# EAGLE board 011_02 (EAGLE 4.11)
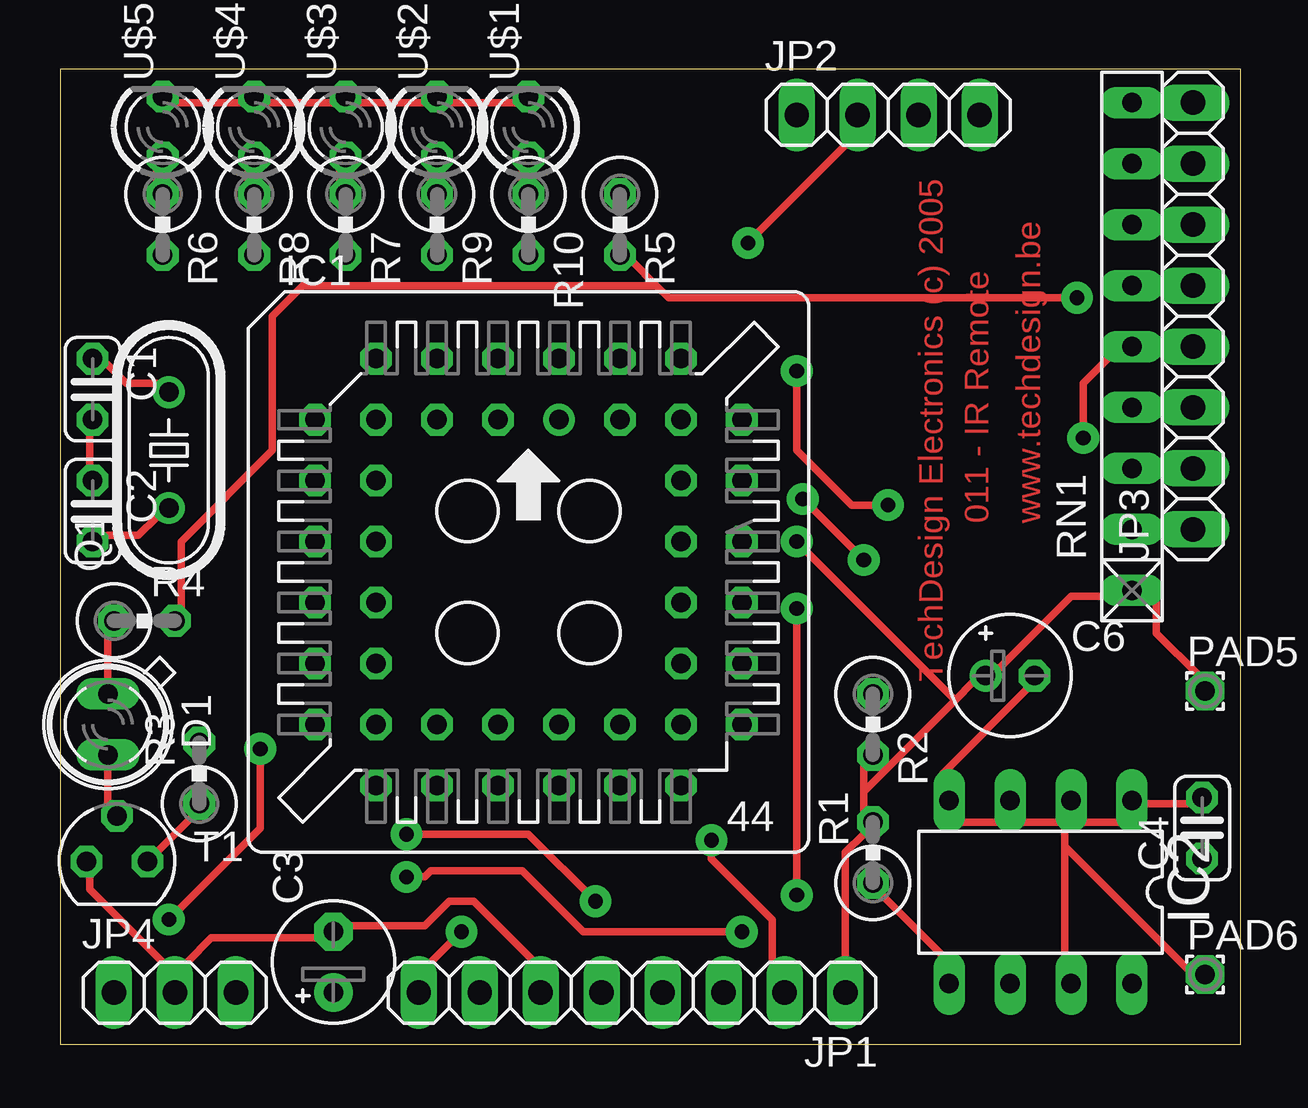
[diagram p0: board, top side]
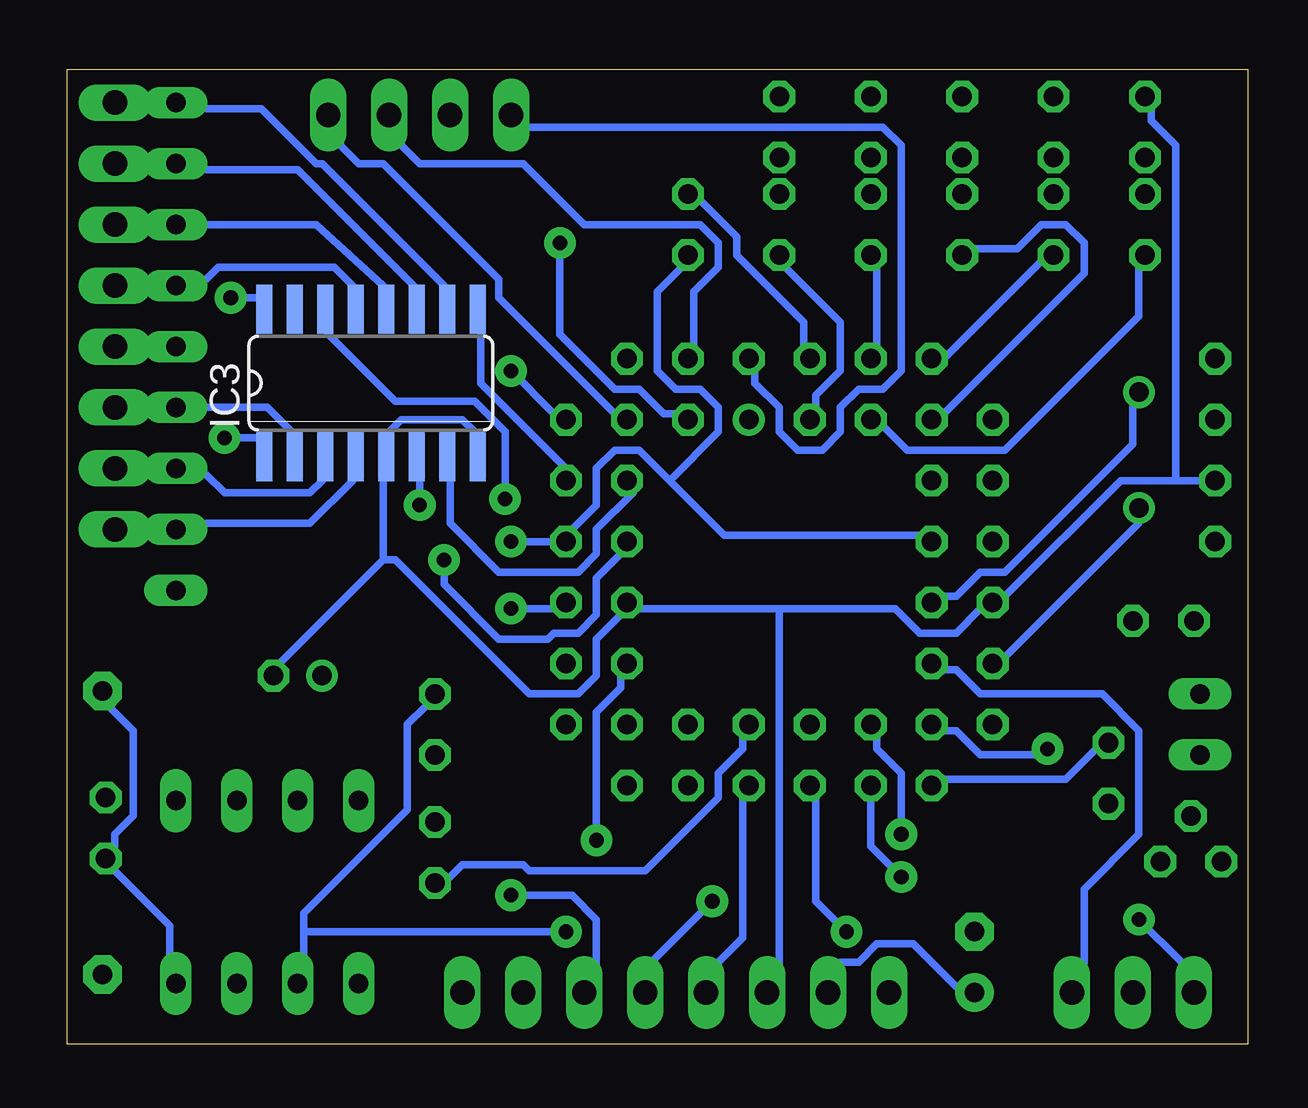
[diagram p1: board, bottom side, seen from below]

Size 49.2 x 40.63 mm. Coordinates in mm from the lower left corner, seen from the top.
Outline: 0,0 49.2,0 49.2,40.63 0,40.63 0,0
Copper layers (1*16): Top 0.035mm / dielectric 1.5mm / Bottom 0.035mm
Design rules "michel4": minimum track width 12mil, minimum drill 24mil, track to track 12mil, track to pad 12mil, pad to pad 12mil, via to via 12mil, smd to smd 10mil, copper to edge 40mil, drill to drill 8mil, minimum pad ring 10mil, minimum via ring 14mil, stop-mask expansion 4mil, vias tented up to drill 0mil, thermal gap 10mil
tRestrict: area 9.1,9.5 to 29.9,30.1; area 31.5,24.3 to 41.9,30.3

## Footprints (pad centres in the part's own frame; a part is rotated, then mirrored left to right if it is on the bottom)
C025-024X044 = drill 0.813 octagon: 1 -1.27,0; 2 1.27,0
E2,5-5 = drill 0.813 pad 1.6 round: + -1.27,0 | drill 0.813 pad 1.6 octagon: - 1.27,0
E2-5 = drill 0.813 pad 1.27 round: + -1.016,0 | drill 0.813 pad 1.27 octagon: - 1.016,0
SFH482 = drill 0.813 long: A -1.27,0; K 1.27,0
S44 = drill 0.813 round: 1 1.27,6.35 | drill 0.813 octagon: 2 -1.27,8.89; 3 -1.27,6.35; 4 -3.81,8.89; 5 -3.81,6.35; 6 -6.35,8.89; 7 -8.89,6.35; 8 -6.35,6.35; 9 -8.89,3.81; 10 -6.35,3.81; 11 -8.89,1.27; 12 -6.35,1.27; 13 -8.89,-1.27; 14 -6.35,-1.27; 15 -8.89,-3.81; 16 -6.35,-3.81; 17 -8.89,-6.35; 18 -6.35,-8.89; 19 -6.35,-6.35; 20 -3.81,-8.89; 21 -3.81,-6.35; 22 -1.27,-8.89; 23 -1.27,-6.35; 24 1.27,-8.89; 25 1.27,-6.35; 26 3.81,-8.89; 27 3.81,-6.35; 28 6.35,-8.89; 29 8.89,-6.35; 30 6.35,-6.35; 31 8.89,-3.81; 32 6.35,-3.81; 33 8.89,-1.27; 34 6.35,-1.27; 35 8.89,1.27; 36 6.35,1.27; 37 8.89,3.81; 38 6.35,3.81; 39 8.89,6.35; 40 6.35,8.89; 41 6.35,6.35; 42 3.81,8.89; 43 3.81,6.35; 44 1.27,8.89
DIL8 = drill 0.813 long: 1 -3.81,-3.81; 2 -1.27,-3.81; 3 1.27,-3.81; 4 3.81,-3.81; 5 3.81,3.81; 6 1.27,3.81; 7 -1.27,3.81; 8 -3.81,3.81
SO16 = smd 0.66 x 2.032: 1 -4.445,-3.073; 2 -3.175,-3.073; 3 -1.905,-3.073; 4 -0.635,-3.073; 5 0.635,-3.073; 6 1.905,-3.073; 7 3.175,-3.073; 8 4.445,-3.073; 9 4.445,3.073; 10 3.175,3.073; 11 1.905,3.073; 12 0.635,3.073; 13 -0.635,3.073; 14 -1.905,3.073; 15 -3.175,3.073; 16 -4.445,3.073
1X08 = drill 1.016 long: 1 -8.89,0; 2 -6.35,0; 3 -3.81,0; 4 -1.27,0; 5 1.27,0; 6 3.81,0; 7 6.35,0; 8 8.89,0
1X04 = drill 1.016 long: 1 -3.81,0; 2 -1.27,0; 3 1.27,0; 4 3.81,0
1X03 = drill 1.016 long: 1 -2.54,0; 2 0,0; 3 2.54,0
1,6/0,8 = drill 0.813 pad 1.6 octagon: 1 0,0
HC49/S = drill 0.813 round: 1 -2.413,0; 2 2.413,0
0309V = drill 0.813 octagon: 1 -1.27,0; 2 1.27,0
RN-9 = drill 0.813 long: 1 -10.16,0; 2 -7.62,0; 3 -5.08,0; 4 -2.54,0; 5 0,0; 6 2.54,0; 7 5.08,0; 8 7.62,0; 9 10.16,0
SOT54D = drill 0.813 octagon: B 1.27,0; C 0,1.905; E -1.27,0
LED3MM = drill 0.813 octagon: A -1.27,0; K 1.27,0

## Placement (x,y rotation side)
C1  22p  [C025-024X044]  1.36,27.3 270 top
C2  22p  [C025-024X044]  1.36,22.22 270 top
C3  µ47  [E2,5-5]  11.39,3.42 90 top
C4  100n  [C025-024X044]  47.59,9.01 90 top
C6  100µ  [E2-5]  39.59,15.36 0 top
D1  SFH482  [SFH482]  1.99,13.33 270 top
IC1  PIC16F877LF  [S44]  19.52,19.68 0 top
IC2  24LC256P  [DIL8]  40.86,6.34 180 top
IC3  74HC148D  [SO16]  36.54,27.55 0 bottom
JP1  LCD LPH7779  [1X08]  23.84,2.15 180 top
JP2  KEY-COL  [1X04]  34.51,38.73 0 top
JP3  KEY-ROW  [1X08]  47.21,30.35 90 top
JP4  TSOP34836  [1X03]  4.79,2.15 0 top
PAD5  [1,6/0,8]  47.71,14.73 0 top
PAD6  [1,6/0,8]  47.71,2.92 0 top
Q1  4 MhZ  [HC49/S]  4.53,24.76 90 top
R1  10k  [0309V]  33.87,8 90 top
R2  10k  [0309V]  33.87,13.33 270 top
R3  220R  [0309V]  5.8,11.3 90 top
R4  4R7  [0309V]  3.52,17.65 0 top
R5  10k  [0309V]  23.33,34.16 270 top
R6  [0309V]  4.28,34.16 270 top
R7  [0309V]  11.9,34.16 270 top
R8  [0309V]  8.09,34.16 270 top
R9  [0309V]  15.71,34.16 270 top
R10  [0309V]  19.52,34.16 270 top
RN1  4k7  [RN-9]  44.67,29.08 90 top
T1  BC639  [SOT54D]  2.38,7.61 0 top
U$1  [LED3MM]  19.52,38.22 90 top
U$2  [LED3MM]  15.71,38.22 90 top
U$3  [LED3MM]  11.9,38.22 90 top
U$4  [LED3MM]  8.09,38.22 90 top
U$5  [LED3MM]  4.28,38.22 90 top

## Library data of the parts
C1-C4 C6 R1-R10 = rcl
D1 U$1-U$5 = led
IC1 = plcc-socket
IC2 = microchip
IC3 = 74xx-eu
JP1-JP4 = pinhead
PAD5 PAD6 = wirepad
Q1 = crystal
RN1 = resistor-net
T1 = transistor-small-signal

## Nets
GND: C1.2 C2.1 C3.- C4.2 C6.- IC1.13 IC1.34 IC2.1 IC2.2 IC2.3 IC2.4 IC2.7 IC3.5 IC3.8 JP1.6 JP4.2 PAD6.1 T1.E U$1.K U$2.K U$3.K U$4.K U$5.K
N$1: IC1.36 IC3.14
N$2: IC1.39 IC3.6
N$3: IC1.38 IC3.7
N$4: IC1.37 IC3.9
N$5: IC3.4 JP3.1 RN1.2
N$6: IC3.2 JP3.3 RN1.4
N$7: IC3.12 JP3.6 RN1.7
N$8: IC3.3 JP3.2 RN1.3
N$9: IC3.13 JP3.5 RN1.6
N$10: IC1.20 IC2.6 R2.1
N$11: IC3.11 JP3.7 RN1.8
N$12: IC3.10 JP3.8 RN1.9
N$13: C2.2 IC1.15 Q1.1
N$14: C1.1 IC1.14 Q1.2
N$15: IC3.1 JP3.4 RN1.5
N$16: IC1.25 IC2.5 R1.1
N$17: IC1.2 R5.1
N$18: IC1.41 JP2.4
N$19: IC1.42 JP2.3
N$20: IC1.43 JP2.2
N$21: IC1.44 JP2.1
N$22: IC1.18 R3.2
N$23: R3.1 T1.B
N$24: D1.K T1.C
N$25: D1.A R4.1
N$26: IC1.16 JP4.3
N$27: IC1.19 JP4.1
N$28: IC1.21 JP1.4
N$29: IC1.22 JP1.8
N$30: IC1.24 JP1.5
N$31: IC1.32 JP1.2
N$32: IC1.33 JP1.3
N$33: C3.+ JP1.7
N$34: IC1.8 R7.2
N$35: IC1.6 R8.2
N$36: IC1.5 R6.2
N$37: IC1.4 R9.2
N$38: IC1.3 R10.2
N$39: R10.1 U$1.A
N$40: R9.1 U$2.A
N$41: R7.1 U$3.A
N$42: R8.1 U$4.A
N$43: R6.1 U$5.A
VDD: C4.1 C6.+ IC1.12 IC1.35 IC2.8 IC3.16 JP1.1 PAD5.1 R1.2 R2.2 R4.2 R5.2 RN1.1

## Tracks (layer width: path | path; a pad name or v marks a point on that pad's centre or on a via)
GND
  Top 0.305: 41.87,8.25 41.87,9.01 IC2.2 | 41.87,8.25 41.87,3.68 IC2.7 | IC2.2 42.63,9.27 44.16,9.27 IC2.1 45.17,10.03 46.95,10.03 C4.2 | 41.87,8.25 46.95,3.17 PAD6.1 | C6.- 40.35,14.85 36.79,11.3 IC2.4 37.55,9.27 39.08,9.27 IC2.3 40.09,9.27 41.62,9.27 IC2.2 | T1.E 1.23,6.98 1.23,6.47 4.28,3.42 JP4.2 5.3,3.42 6.31,4.44 10.63,4.44 C3.- 12.15,4.95 15.2,4.95 16.22,5.96 17.23,5.96 19.77,3.42 JP1.6 | U$5.K 4.79,39.24 7.58,39.24 U$4.K 8.6,39.24 11.39,39.24 U$3.K 12.41,39.24 15.2,39.24 U$2.K 16.22,39.24 19.01,39.24 U$1.K | C2.1 1.23,24 1.23,25.52 C1.2
  Bottom 0.305: IC3.8 32.22,25.27 32.22,25.52 32.73,26.03 35.27,26.03 36.03,25.27 IC3.5 36.03,23.49 36.03,20.19 | 36.03,20.19 40.35,15.87 C6.- | 3.01,23.49 5.3,23.49 10.12,18.66 IC1.13 11.14,18.16 12.15,17.14 13.68,17.14 14.69,18.16 19.52,18.16 | 3.01,23.49 C2.1 | 19.52,18.16 25.36,18.16 IC1.34 26.12,17.9 27.14,16.89 27.14,15.36 27.9,14.6 29.93,14.6 35.52,20.19 36.03,20.19 | 19.52,18.16 19.52,3.42 JP1.6 | 3.01,23.49 3.01,37.46 4.03,38.48 4.03,38.98 U$5.K
N$1  (via drill 0.61)
  Top 0.305: v33.49,20.19 v30.95,22.73
  Bottom 0.305: v30.95,22.73 30.95,25.52 32.22,26.79 35.52,26.79 38.32,29.59 38.32,29.84 IC3.14 | v33.49,20.19 33.49,19.17 31.2,16.89 29.17,16.89 28.92,17.14 27.9,17.14 27.14,17.9 27.14,19.43 26.12,20.44 IC1.36
N$2  (via drill 0.61)
  Top 0.305: v34.51,22.47 32.98,22.47 30.7,24.76 v30.7,28.06
  Bottom 0.305: v34.51,22.47 34.51,23.49 IC3.6 | v30.7,28.06 28.92,26.28 IC1.39
N$3
  Bottom 0.305: IC3.7 33.24,23.49 33.24,21.71 31.2,19.68 27.9,19.68 27.14,20.44 27.14,21.46 25.62,22.98 IC1.38
N$4
  Bottom 0.305: IC3.9 31.97,29.84 31.97,27.55 28.41,24 IC1.37
N$5
  Top 0.305: JP3.1 45.94,21.2 RN1.2
  Bottom 0.305: IC3.4 37.3,23.49 39.08,21.71 43.4,21.71 RN1.2
N$6
  Top 0.305: JP3.3 45.94,26.28 RN1.4
  Bottom 0.305: IC3.2 39.84,25.27 39.84,25.52 40.86,26.54 RN1.4
N$7
  Top 0.305: JP3.6 45.94,33.9 RN1.7
  Bottom 0.305: IC3.12 36.03,31.62 38.82,34.16 RN1.7
N$8
  Top 0.305: JP3.2 45.94,23.74 RN1.3
  Bottom 0.305: IC3.3 38.57,23.49 39.08,22.98 42.63,22.98 43.4,23.74 RN1.3
N$9
  Top 0.305: JP3.5 45.94,31.36 RN1.6
  Bottom 0.305: IC3.13 37.3,31.62 38.06,32.38 42.89,32.38 43.4,31.87 RN1.6
N$10  (via drill 0.61)
  Top 0.305: v14.44,6.98 15.2,6.98 15.46,7.23 19.27,7.23 21.81,4.69 v28.41,4.69
  Bottom 0.305: 39.33,4.69 39.33,5.46 35.01,9.77 35.01,13.33 34.25,14.09 R2.1 | 39.33,4.69 39.33,3.68 IC2.6 | v14.44,6.98 15.71,8.25 IC1.20 | v28.41,4.69 39.33,4.69
N$11
  Top 0.305: JP3.7 45.94,36.44 RN1.8
  Bottom 0.305: IC3.11 34.76,31.62 39.59,36.44 43.4,36.44 RN1.8
N$12
  Top 0.305: JP3.8 45.94,38.98 RN1.9
  Bottom 0.305: IC3.10 33.49,31.62 38.57,36.7 38.82,36.7 41.11,38.98 43.4,38.98 RN1.9
N$13
  Top 0.305: C2.2 1.99,21.2 3.26,21.2 4.03,21.97 Q1.1
  Bottom 0.305: IC1.15 10.12,16.12 4.53,21.71 Q1.1
N$14
  Top 0.305: Q1.2 4.03,27.55 2.76,27.55 1.99,28.32 C1.1
  Bottom 0.305: IC1.14 12.66,18.66 12.15,18.66 11.14,19.68 10.12,19.68 4.79,25.01 4.79,26.54 Q1.2
N$15  (via drill 0.61)
  Top 0.305: v42.63,25.27 42.63,27.55 43.65,28.57 RN1.5 45.94,28.82 JP3.4
  Bottom 0.305: v42.63,25.27 41.11,25.27 IC3.1
N$16
  Top 0.305: R1.1 34.25,6.22 36.79,3.68 IC2.5
  Bottom 0.305: IC1.25 21.04,12.82 21.04,12.31 22.06,11.3 22.06,10.28 25.11,7.23 29.93,7.23 30.19,7.49 32.73,7.49 33.24,6.98 R1.1
N$17
  Bottom 0.305: IC1.2 18.5,29.08 18.5,30.09 21.3,32.89 21.3,33.65 22.82,35.17 R5.1
N$18
  Bottom 0.305: IC1.41 26.38,26.28 31.2,31.11 31.2,31.87 36.03,36.7 37.05,36.7 37.81,37.46 JP2.4
N$19
  Bottom 0.305: IC1.42 23.08,29.08 23.08,31.36 22.06,32.38 22.06,33.4 22.82,34.16 27.65,34.16 30.19,36.7 34.51,36.7 35.27,37.46 JP2.3
N$20  (via drill 0.61)
  Top 0.305: v28.66,33.4 32.73,37.46 JP2.2
  Bottom 0.305: v28.66,33.4 28.66,29.59 26.38,27.3 25.36,27.3 24.35,26.28 23.84,26.28 IC1.43
N$21
  Bottom 0.305: IC1.44 20.54,28.06 20.54,27.55 19.52,26.54 19.52,25.52 18.76,24.76 17.74,24.76 16.98,25.52 16.98,26.54 16.22,27.3 15.2,27.3 14.44,28.06 14.44,37.46 15.2,38.22 30.19,38.22 JP2.1
N$22
  Bottom 0.305: IC1.18 12.66,11.04 7.58,11.04 6.31,12.31 R3.2
N$23
  Top 0.305: T1.B 5.55,9.52 R3.1
N$24
  Top 0.305: T1.C 1.99,10.03 D1.K
N$25
  Top 0.305: D1.A 1.99,17.14 R4.1
N$26
  Bottom 0.305: IC1.16 12.66,15.62 12.15,15.62 11.14,14.6 6.06,14.6 4.53,13.08 4.53,8.76 6.82,6.47 6.82,3.42 JP4.3
N$27  (via drill 0.61)
  Top 0.305: v8.34,12.31 8.34,9.01 v4.53,5.2
  Bottom 0.305: v8.34,12.31 8.6,12.06 11.14,12.06 12.15,13.08 12.66,13.08 IC1.19 | v4.53,5.2 2.76,3.42 JP4.1
N$28  (via drill 0.61)
  Top 0.305: v14.44,8.76 19.52,8.76 v22.31,5.96
  Bottom 0.305: v14.44,8.76 14.44,11.3 15.46,12.31 15.46,12.82 IC1.21 | v22.31,5.96 24.85,3.42 JP1.4
N$29  (via drill 0.61)
  Top 0.305: v16.73,4.69 15.46,3.42 JP1.8
  Bottom 0.305: v16.73,4.69 18,5.96 18,10.28 IC1.22
N$30
  Bottom 0.305: IC1.24 21.04,10.28 21.04,4.44 22.06,3.42 JP1.5
N$31  (via drill 0.61)
  Top 0.305: v27.14,8.5 27.14,7.74 29.68,5.2 29.68,3.42 JP1.2
  Bottom 0.305: v27.14,8.5 27.14,13.84 26.12,14.85 26.12,15.36 IC1.32
N$32  (via drill 0.61)
  Top 0.305: v30.7,6.22 v30.7,18.16
  Bottom 0.305: v30.7,18.16 28.92,18.16 IC1.33 | v30.7,6.22 28.16,6.22 27.14,5.2 27.14,3.42 JP1.3
N$33
  Bottom 0.305: JP1.7 16.98,3.42 16.22,3.42 15.46,4.19 13.93,4.19 12.15,2.41 C3.+
N$34
  Bottom 0.305: R7.2 11.39,33.14 9.61,33.14 8.6,34.16 7.58,34.16 6.82,33.4 6.82,32.13 12.66,26.28 IC1.8
N$35
  Bottom 0.305: R8.2 8.6,32.63 12.66,28.57 IC1.6
N$36
  Bottom 0.305: R6.2 4.53,32.38 4.53,30.35 10.12,24.76 14.19,24.76 15.2,25.78 IC1.5
N$37
  Bottom 0.305: IC1.4 15.46,29.08 15.46,32.38 R9.2
N$38
  Bottom 0.305: IC1.3 18,26.54 18,27.05 16.98,28.06 16.98,30.09 19.27,32.38 R10.2
N$39
  Top 0.305: R10.1 19.27,35.94 19.27,36.44 U$1.A
N$40
  Top 0.305: R9.1 15.46,35.94 15.46,36.44 U$2.A
N$41
  Top 0.305: R7.1 11.65,35.94 11.65,36.44 U$3.A
N$42
  Top 0.305: R8.1 7.84,35.94 7.84,36.44 U$4.A
N$43
  Top 0.305: R6.1 4.03,35.94 4.03,36.44 U$5.A
VDD  (via drill 0.61)
  Top 0.305: PAD5.1 47.46,15.36 45.68,17.14 45.68,18.41 RN1.1 43.4,18.66 42.13,18.66 39.08,15.62 C6.+ 38.06,15.11 37.3,14.35 | 33.49,10.54 33.49,11.55 R2.2 | 33.49,10.54 33.49,9.77 R1.2 33.49,8.76 32.73,8 JP1.1 | 37.3,14.35 33.49,10.54 | v42.38,31.11 25.36,31.11 24.85,31.62 | 24.85,31.62 23.84,32.63 R5.2 | 24.85,31.62 10.12,31.62 8.85,30.35 8.85,24.76 5.04,20.95 5.04,18.16 R4.2 | v30.7,20.95 37.3,14.35
  Bottom 0.305: IC2.8 44.92,3.68 44.92,4.95 47.21,7.23 C4.1 47.21,8.25 47.21,8.76 46.44,9.52 46.44,13.08 47.46,14.09 PAD5.1 | 24.09,23.49 25.36,24.76 26.38,24.76 27.14,24 27.14,22.47 28.16,21.46 IC1.35 v30.7,20.95 | 24.09,23.49 21.81,21.2 13.68,21.2 IC1.12 | v42.38,31.11 41.11,31.11 IC3.16 | 24.09,23.49 22.06,25.52 22.06,26.54 22.82,27.3 23.84,27.3 24.6,28.06 24.6,31.36 23.58,32.38 R5.2

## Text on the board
Top: TechDesign Electronics (c) 2005 | 011 - IR Remote | www.techdesign.be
